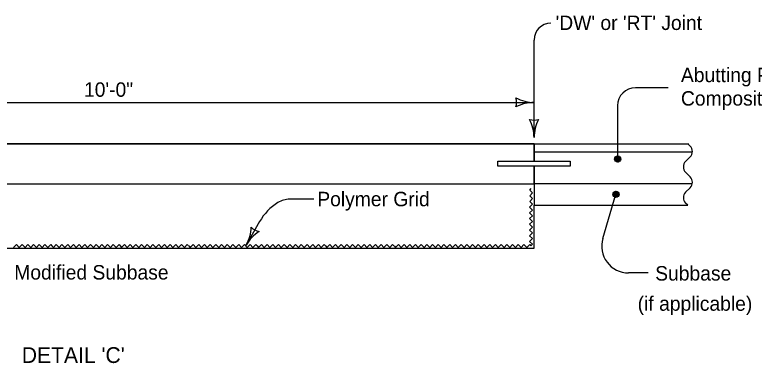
# Model space of a CAD drawing. Extents: x -2135039 to -2124495, y -2139046 to -2132546.
# Drawn here: x -2130034 to -2129213, y -2133904 to -2133518 of the extents above; entities that cross this region are included whole.
import ezdxf

# ---------------------------------------------------------------- set-up
doc = ezdxf.new("R2010")
doc.units = 0
doc.layers.add('BridgeSuperStructureExisting', color=7, linetype='Continuous')
doc.layers.add('dsnStdLabel', color=7, linetype='Continuous')

msp = doc.modelspace()

# ---------------------------------------------------------------- linework, layer by layer
at = {"layer": 'BridgeSuperStructureExisting'}
for p, q in [((-2129457.45, -2133654.25), (-2129457.45, -2133546.05)), ((-2129308.47, -2133599.02), (-2129344.94, -2133599.02)), ((-2130384.09, -2133615.29), (-2129457.45, -2133615.29)), ((-2129364.74, -2133618.82), (-2129364.74, -2133678.11)), ((-2129457.45, -2133661.05), (-2130373.93, -2133661.05)), ((-2130373.93, -2133661.05), (-2129457.45, -2133661.05)), ((-2129457.45, -2133680.54), (-2129457.45, -2133661.05)), ((-2129457.45, -2133661.05), (-2129457.45, -2133680.54)), ((-2129457.45, -2133661.05), (-2129457.45, -2133680.54)), ((-2129457.45, -2133661.05), (-2129285.73, -2133661.05)), ((-2129284.19, -2133663.65), (-2129286.69, -2133661.15)), ((-2129457.45, -2133669.91), (-2129281.7, -2133669.91)), ((-2129497.55, -2133686.11), (-2129497.55, -2133680.54)), ((-2129497.55, -2133680.54), (-2129457.45, -2133680.54)), ((-2129497.54, -2133686.11), (-2129497.54, -2133680.54)), ((-2129497.54, -2133680.54), (-2129417.35, -2133680.54)), ((-2129417.35, -2133680.54), (-2129417.35, -2133686.11)), ((-2129289.19, -2133680.7), (-2129284.19, -2133675.7)), ((-2129457.45, -2133686.11), (-2129497.55, -2133686.11)), ((-2129417.35, -2133686.11), (-2129497.54, -2133686.11)), ((-2129457.45, -2133705.6), (-2129457.45, -2133686.11)), ((-2129457.45, -2133686.11), (-2129457.45, -2133705.6)), ((-2129286.69, -2133695.26), (-2129289.19, -2133692.76)), ((-2129284.19, -2133697.75), (-2129286.69, -2133695.26)), ((-2130332.86, -2133705.6), (-2129457.45, -2133705.6)), ((-2130332.86, -2133705.6), (-2129457.45, -2133705.6)), ((-2129457.45, -2133705.6), (-2129457.45, -2133729.36)), ((-2129282.71, -2133705.6), (-2129457.45, -2133705.6)), ((-2129289.19, -2133714.81), (-2129284.19, -2133709.81)), ((-2129702.03, -2133722.62), (-2129728.63, -2133722.62)), ((-2129381.09, -2133766.15), (-2129366.51, -2133717.18)), ((-2129457.45, -2133741.81), (-2129457.45, -2133729.36)), ((-2129457.45, -2133729.36), (-2129286.69, -2133729.36)), ((-2129286.69, -2133729.36), (-2129289.19, -2133726.86)), ((-2129762.09, -2133747.34), (-2129777.06, -2133773.48)), ((-2129457.45, -2133776.88), (-2129457.45, -2133741.81)), ((-2130354.39, -2133776.88), (-2129457.45, -2133776.88)), ((-2129330.91, -2133804.33), (-2129352.63, -2133804.33))]:
    msp.add_line(p, q, dxfattribs=at)
for points in [[(-2129361.55, -2133678.38), (-2129362.08, -2133677.21), (-2129362.65, -2133675.39), (-2129364.49, -2133675.03), (-2129366.11, -2133675.29), (-2129367.61, -2133676.45), (-2129367.45, -2133678.18), (-2129367.2, -2133680.01), (-2129365.75, -2133680.88), (-2129364.21, -2133681.04), (-2129362.21, -2133679.97), (-2129362.04, -2133678.63), (-2129362.5, -2133676.81), (-2129363.67, -2133675.32), (-2129365.39, -2133675.37), (-2129366.79, -2133676.53), (-2129366.95, -2133678.16), (-2129366.59, -2133679.99), (-2129365.56, -2133680.27), (-2129364.32, -2133680.63), (-2129362.82, -2133679.78), (-2129362.86, -2133678.46), (-2129363.11, -2133676.94), (-2129363.96, -2133675.83), (-2129365.47, -2133676.39), (-2129366.35, -2133677.54), (-2129366.41, -2133679.07), (-2129365.58, -2133679.45), (-2129364.66, -2133679.93), (-2129363.45, -2133679.19), (-2129363.18, -2133678.06), (-2129363.72, -2133677.05), (-2129364.84, -2133676.98), (-2129365.64, -2133677.51), (-2129365.92, -2133678.54), (-2129365.5, -2133679.04), (-2129364.87, -2133679.33), (-2129363.98, -2133678.79), (-2129363.79, -2133678.08), (-2129364.22, -2133677.37), (-2129364.82, -2133677.49), (-2129365.22, -2133678.01), (-2129365.2, -2133678.73), (-2129364.69, -2133678.71), (-2129364.4, -2133678.09)], [(-2129460.87, -2133774.21), (-2129459.28, -2133772.64), (-2129462.44, -2133769.45), (-2129459.26, -2133766.3), (-2129462.42, -2133763.12), (-2129459.24, -2133759.96), (-2129462.4, -2133756.79), (-2129459.22, -2133753.63), (-2129462.39, -2133750.45), (-2129459.21, -2133747.29), (-2129462.37, -2133744.11), (-2129459.19, -2133740.95), (-2129462.35, -2133737.77), (-2129459.17, -2133734.62), (-2129462.33, -2133731.44), (-2129459.16, -2133728.28), (-2129462.32, -2133725.11), (-2129459.14, -2133721.95), (-2129462.3, -2133718.77), (-2129459.13, -2133715.61), (-2129462.28, -2133712.43), (-2129460.64, -2133710.8)], [(-2129366.24, -2133714.01), (-2129367.41, -2133714.53), (-2129369.23, -2133715.09), (-2129369.58, -2133716.94), (-2129369.33, -2133718.56), (-2129368.17, -2133720.06), (-2129366.44, -2133719.91), (-2129364.61, -2133719.65), (-2129363.74, -2133718.2), (-2129363.58, -2133716.66), (-2129364.65, -2133714.66), (-2129365.98, -2133714.49), (-2129367.81, -2133714.95), (-2129369.3, -2133716.12), (-2129369.25, -2133717.85), (-2129368.09, -2133719.24), (-2129366.46, -2133719.39), (-2129364.63, -2133719.04), (-2129364.35, -2133718.01), (-2129363.98, -2133716.78), (-2129364.84, -2133715.27), (-2129366.16, -2133715.31), (-2129367.68, -2133715.56), (-2129368.78, -2133716.41), (-2129368.23, -2133717.92), (-2129367.08, -2133718.8), (-2129365.55, -2133718.86), (-2129365.17, -2133718.03), (-2129364.69, -2133717.11), (-2129365.43, -2133715.9), (-2129366.56, -2133715.63), (-2129367.56, -2133716.17), (-2129367.64, -2133717.29), (-2129367.1, -2133718.09), (-2129366.07, -2133718.37), (-2129365.58, -2133717.95), (-2129365.29, -2133717.32), (-2129365.83, -2133716.42), (-2129366.54, -2133716.24), (-2129367.25, -2133716.67), (-2129367.13, -2133717.28), (-2129366.61, -2133717.67), (-2129365.89, -2133717.64), (-2129365.91, -2133717.14), (-2129366.53, -2133716.85)], [(-2130035.22, -2133776.07), (-2130032.04, -2133772.91), (-2130028.89, -2133776.09), (-2130025.7, -2133772.93), (-2130022.54, -2133776.1), (-2130019.38, -2133772.94), (-2130016.22, -2133776.12), (-2130013.04, -2133772.96), (-2130009.88, -2133776.14), (-2130006.7, -2133772.98), (-2130003.54, -2133776.15), (-2130000.37, -2133772.99), (-2129997.21, -2133776.18), (-2129994.03, -2133773.01), (-2129992.61, -2133774.14)], [(-2129992.61, -2133774.39), (-2129991.04, -2133775.99), (-2129987.85, -2133772.82), (-2129984.7, -2133776), (-2129981.52, -2133772.84), (-2129978.36, -2133776.02), (-2129975.19, -2133772.86), (-2129972.03, -2133776.04), (-2129968.84, -2133772.88), (-2129965.69, -2133776.06), (-2129962.51, -2133772.89), (-2129959.35, -2133776.07), (-2129956.17, -2133772.91), (-2129953.02, -2133776.09), (-2129949.84, -2133772.93), (-2129946.68, -2133776.1), (-2129943.51, -2133772.94), (-2129940.35, -2133776.12), (-2129937.17, -2133772.96), (-2129934.01, -2133776.14), (-2129930.83, -2133772.98), (-2129927.68, -2133776.15), (-2129924.5, -2133772.99), (-2129921.34, -2133776.18), (-2129918.16, -2133773.01), (-2129916.74, -2133774.14)], [(-2129916.93, -2133774.39), (-2129915.35, -2133775.99), (-2129912.17, -2133772.82), (-2129909.01, -2133776), (-2129905.83, -2133772.84), (-2129902.67, -2133776.02), (-2129899.5, -2133772.86), (-2129896.34, -2133776.04), (-2129893.16, -2133772.88), (-2129890.01, -2133776.06), (-2129886.82, -2133772.89), (-2129883.66, -2133776.07), (-2129880.49, -2133772.91), (-2129877.33, -2133776.09), (-2129874.15, -2133772.93), (-2129870.99, -2133776.1), (-2129867.82, -2133772.94), (-2129864.66, -2133776.12), (-2129861.49, -2133772.96), (-2129858.33, -2133776.14), (-2129855.14, -2133772.98), (-2129851.99, -2133776.15), (-2129848.81, -2133772.99), (-2129845.65, -2133776.18), (-2129842.48, -2133773.01), (-2129841.05, -2133774.14)], [(-2129840.8, -2133774.39), (-2129839.22, -2133775.99), (-2129836.04, -2133772.82), (-2129832.89, -2133776), (-2129829.71, -2133772.84), (-2129826.55, -2133776.02), (-2129823.38, -2133772.86), (-2129820.22, -2133776.04), (-2129817.03, -2133772.88), (-2129813.88, -2133776.06), (-2129810.7, -2133772.89), (-2129807.54, -2133776.07), (-2129804.36, -2133772.91), (-2129801.21, -2133776.09), (-2129798.03, -2133772.93), (-2129794.87, -2133776.1), (-2129791.7, -2133772.94), (-2129788.54, -2133776.12), (-2129785.36, -2133772.96), (-2129782.2, -2133776.14), (-2129779.02, -2133772.98), (-2129775.87, -2133776.15), (-2129772.69, -2133772.99), (-2129769.53, -2133776.18), (-2129766.35, -2133773.01), (-2129764.93, -2133774.14)], [(-2129764.94, -2133774.39), (-2129763.36, -2133775.99), (-2129760.18, -2133772.82), (-2129757.03, -2133776), (-2129753.84, -2133772.84), (-2129750.68, -2133776.02), (-2129747.52, -2133772.86), (-2129744.36, -2133776.04), (-2129741.17, -2133772.88), (-2129738.02, -2133776.06), (-2129734.84, -2133772.89), (-2129731.68, -2133776.07), (-2129728.5, -2133772.91), (-2129725.35, -2133776.09), (-2129722.16, -2133772.93), (-2129719, -2133776.1), (-2129715.84, -2133772.94), (-2129712.68, -2133776.12), (-2129709.5, -2133772.96), (-2129706.34, -2133776.14), (-2129703.16, -2133772.98), (-2129700, -2133776.15), (-2129696.83, -2133772.99), (-2129693.67, -2133776.18), (-2129690.49, -2133773.01), (-2129689.07, -2133774.14)], [(-2129689, -2133774.39), (-2129687.42, -2133775.99), (-2129684.24, -2133772.82), (-2129681.09, -2133776), (-2129677.9, -2133772.84), (-2129674.74, -2133776.02), (-2129671.57, -2133772.86), (-2129668.41, -2133776.04), (-2129665.23, -2133772.88), (-2129662.08, -2133776.06), (-2129658.89, -2133772.89), (-2129655.73, -2133776.07), (-2129652.56, -2133772.91), (-2129649.41, -2133776.09), (-2129646.22, -2133772.93), (-2129643.06, -2133776.1), (-2129639.89, -2133772.94), (-2129636.73, -2133776.12), (-2129633.56, -2133772.96), (-2129630.4, -2133776.14), (-2129627.21, -2133772.98), (-2129624.06, -2133776.15), (-2129620.89, -2133772.99), (-2129617.73, -2133776.18), (-2129614.55, -2133773.01), (-2129613.12, -2133774.14)], [(-2129612.87, -2133774.39), (-2129611.3, -2133775.99), (-2129608.11, -2133772.82), (-2129604.96, -2133776), (-2129601.78, -2133772.84), (-2129598.62, -2133776.02), (-2129595.45, -2133772.86), (-2129592.29, -2133776.04), (-2129589.11, -2133772.88), (-2129585.95, -2133776.06), (-2129582.77, -2133772.89), (-2129579.61, -2133776.07), (-2129576.43, -2133772.91), (-2129573.28, -2133776.09), (-2129570.1, -2133772.93), (-2129566.94, -2133776.1), (-2129563.77, -2133772.94), (-2129560.61, -2133776.12), (-2129557.43, -2133772.96), (-2129554.27, -2133776.14), (-2129551.09, -2133772.98), (-2129547.94, -2133776.15), (-2129544.76, -2133772.99), (-2129541.6, -2133776.18), (-2129538.43, -2133773.01), (-2129537, -2133774.14)], [(-2129536.74, -2133774.39), (-2129535.16, -2133775.99), (-2129531.98, -2133772.82), (-2129528.82, -2133776), (-2129525.64, -2133772.84), (-2129522.48, -2133776.02), (-2129519.31, -2133772.86), (-2129516.15, -2133776.04), (-2129512.97, -2133772.88), (-2129509.81, -2133776.06), (-2129506.63, -2133772.89), (-2129503.47, -2133776.07), (-2129500.3, -2133772.91), (-2129497.14, -2133776.09), (-2129493.96, -2133772.93), (-2129490.8, -2133776.1), (-2129487.63, -2133772.94), (-2129484.47, -2133776.12), (-2129481.3, -2133772.96), (-2129478.13, -2133776.14), (-2129474.95, -2133772.98), (-2129471.8, -2133776.15), (-2129468.62, -2133772.99), (-2129465.46, -2133776.18), (-2129462.29, -2133773.01), (-2129460.86, -2133774.14)]]:
    msp.add_lwpolyline(points, dxfattribs=at)
for centre in [(-2129364.74, -2133678.11), (-2129366.51, -2133717.18)]:
    msp.add_circle(centre, 3.46, dxfattribs=at)
for centre, radius, start, end in [((-2129438.89, -2133546.05), 18.56, 90, 180), ((-2129344.94, -2133618.82), 19.8, 90, 180), ((-2129493.29, -2133615.28), 16.51, 342.26665, 17.73335), ((-2129457.45, -2133572.54), 42.75, 241.92751, 270), ((-2129493.29, -2133615.28), 16.51, 342.26665, 17.73335), ((-2129457.45, -2133572.54), 42.75, 241.92751, 270), ((-2129457.45, -2133658.03), 42.75, 90, 118.07249), ((-2129457.45, -2133658.03), 42.75, 90, 118.07249), ((-2129457.45, -2133618.4), 16.51, 252.26665, 287.73335), ((-2129500.2, -2133654.25), 42.75, 360, 28.07249), ((-2129457.45, -2133618.4), 16.51, 252.26665, 287.73335), ((-2129500.2, -2133654.25), 42.75, 360, 28.07249), ((-2129414.7, -2133654.25), 42.75, 151.92751, 180), ((-2129414.7, -2133654.25), 42.75, 151.92751, 180), ((-2129290.22, -2133669.67), 8.53, 315, 45), ((-2129283.16, -2133686.73), 8.53, 135, 225), ((-2129290.22, -2133703.78), 8.53, 315, 45), ((-2129283.16, -2133720.83), 8.53, 135, 225), ((-2129728.63, -2133747.62), 25, 90, 121.71831), ((-2129710.55, -2133776.88), 59.4, 121.71831, 150.17827), ((-2129814.15, -2133752.22), 42.75, 330.17945, 358.25194), ((-2129759.24, -2133742.38), 16.51, 222.4461, 257.9128), ((-2129739.98, -2133794.74), 42.75, 122.10696, 150.17945), ((-2129352.63, -2133774.63), 29.7, 163.41722, 270)]:
    msp.add_arc(centre, radius, start, end, dxfattribs=at)

# ---------------------------------------------------------------- texts
msp.add_text("DETAIL 'C'", height=17.5, dxfattribs=at).set_placement((-2130026.11, -2133904.22))
at = {"layer": 'dsnStdLabel'}
for s, p in [("'DW' or 'RT' Joint", (-2129433.54, -2133534.94)), ('Abutting PCC or', (-2129294.39, -2133592.77)), ('10\'-0"', (-2129957.07, -2133609.01)), ('Composite Pavement', (-2129294.39, -2133618.77)), ('Polymer Grid', (-2129698.09, -2133730.42)), ('Modified Subbase', (-2130034.47, -2133811.68)), ('Subbase', (-2129322.97, -2133812.8)), ('(if applicable)', (-2129342.41, -2133846.32))]:
    msp.add_text(s, height=16, dxfattribs=at).set_placement(p)

doc.saveas('drawing.dxf')
